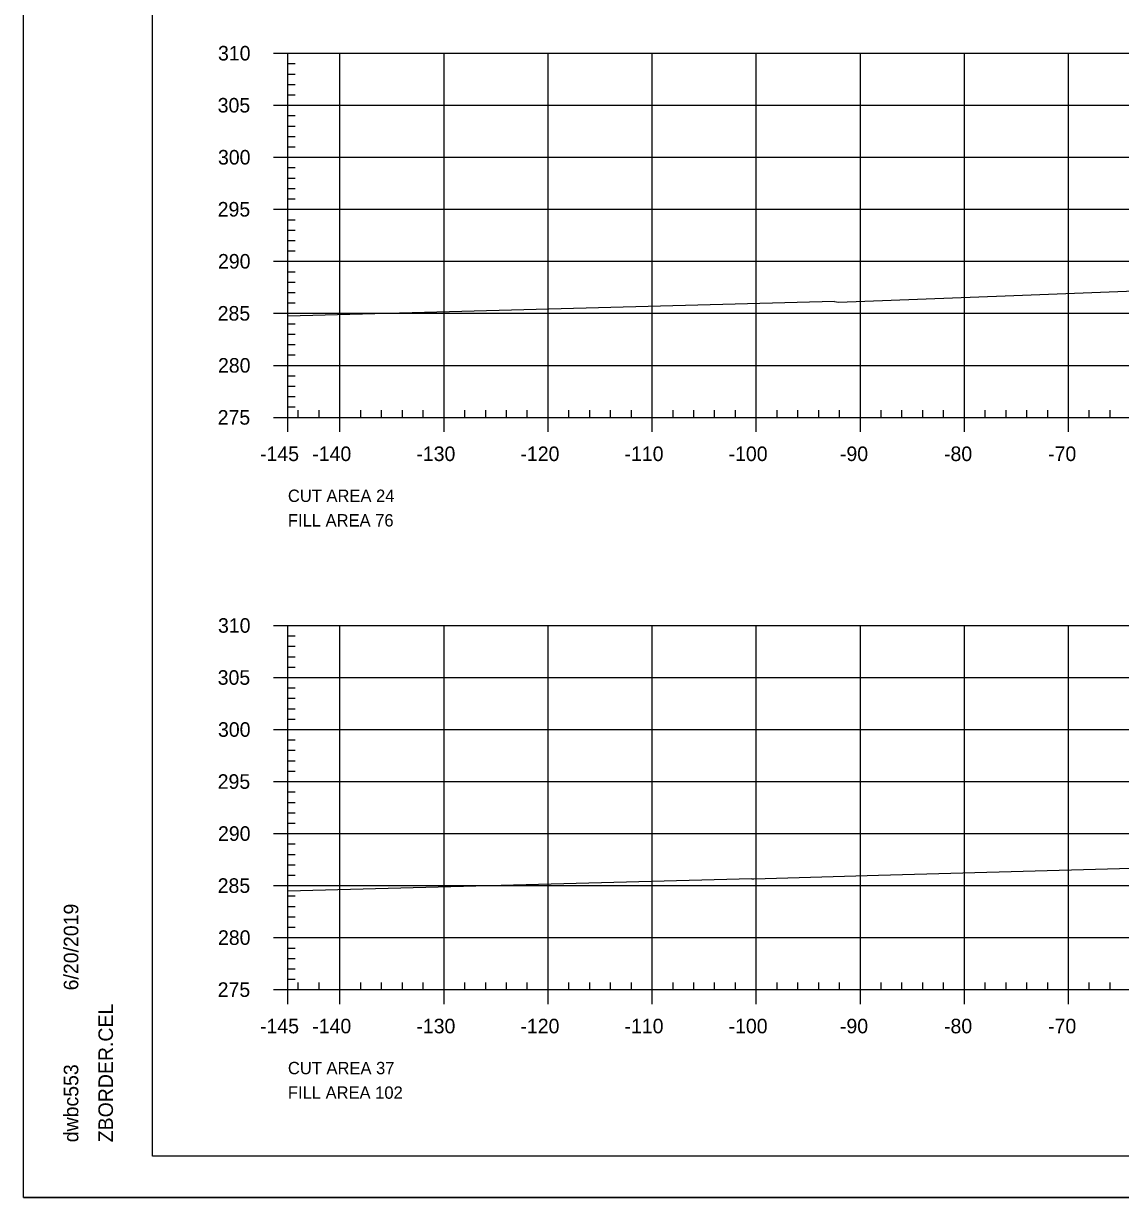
# Model space of a CAD drawing. Extents: x 1370843 to 1371177, y 380307 to 382654.
# Drawn here: x 1370843.3 to 1370948.7, y 382014.2 to 382127 of the extents above; entities that cross this region are included whole.
import ezdxf

# ---------------------------------------------------------------- set-up
doc = ezdxf.new("R2010")
doc.units = 0
for name, color, linetype in [('R_Axis', 7, 'Continuous'), ('R_Axis Annot', 7, 'Continuous'), ('R_Border', 7, 'Continuous'), ('R_Border Notes', 7, 'Continuous'), ('R_Exist Surface', 7, 'Continuous'), ('R_Grid', 7, 'Continuous'), ('R_No Plot', 7, 'Continuous')]:
    doc.layers.add(name, color=color, linetype=linetype)

msp = doc.modelspace()

# ---------------------------------------------------------------- linework, layer by layer
at = {"layer": 'R_Axis'}
for p, q in [((1370867.31, 382124.15), (1370868.71, 382124.15)), ((1370868.71, 382089.15), (1370868.71, 382124.15)), ((1370868.71, 382123.15), (1370869.41, 382123.15)), ((1370868.71, 382122.15), (1370869.41, 382122.15)), ((1370868.71, 382121.15), (1370869.41, 382121.15)), ((1370868.71, 382120.15), (1370869.41, 382120.15)), ((1370867.31, 382119.15), (1370868.71, 382119.15)), ((1370868.71, 382118.15), (1370869.41, 382118.15)), ((1370868.71, 382117.15), (1370869.41, 382117.15)), ((1370868.71, 382116.15), (1370869.41, 382116.15)), ((1370867.31, 382114.15), (1370868.71, 382114.15)), ((1370868.71, 382115.15), (1370869.41, 382115.15)), ((1370868.71, 382113.15), (1370869.41, 382113.15)), ((1370868.71, 382112.15), (1370869.41, 382112.15)), ((1370868.71, 382111.15), (1370869.41, 382111.15)), ((1370868.71, 382110.15), (1370869.41, 382110.15)), ((1370867.31, 382109.15), (1370868.71, 382109.15)), ((1370868.71, 382108.15), (1370869.41, 382108.15)), ((1370868.71, 382107.15), (1370869.41, 382107.15)), ((1370868.71, 382106.15), (1370869.41, 382106.15)), ((1370868.71, 382105.15), (1370869.41, 382105.15)), ((1370867.31, 382104.15), (1370868.71, 382104.15)), ((1370868.71, 382103.15), (1370869.41, 382103.15)), ((1370868.71, 382102.15), (1370869.41, 382102.15)), ((1370868.71, 382101.15), (1370869.41, 382101.15)), ((1370868.71, 382100.15), (1370869.41, 382100.15)), ((1370867.31, 382099.15), (1370868.71, 382099.15)), ((1370868.71, 382098.15), (1370869.41, 382098.15)), ((1370868.71, 382097.15), (1370869.41, 382097.15)), ((1370868.71, 382096.15), (1370869.41, 382096.15)), ((1370868.71, 382095.15), (1370869.41, 382095.15)), ((1370867.31, 382094.15), (1370868.71, 382094.15)), ((1370868.71, 382093.15), (1370869.41, 382093.15)), ((1370868.71, 382092.15), (1370869.41, 382092.15)), ((1370868.71, 382091.15), (1370869.41, 382091.15)), ((1370868.71, 382090.15), (1370869.41, 382090.15)), ((1370868.71, 382089.15), (1370868.71, 382089.85)), ((1370869.71, 382089.15), (1370869.71, 382089.85)), ((1370871.71, 382089.15), (1370871.71, 382089.85)), ((1370875.71, 382089.15), (1370875.71, 382089.85)), ((1370877.71, 382089.15), (1370877.71, 382089.85)), ((1370879.71, 382089.15), (1370879.71, 382089.85)), ((1370881.71, 382089.15), (1370881.71, 382089.85)), ((1370885.71, 382089.15), (1370885.71, 382089.85)), ((1370887.71, 382089.15), (1370887.71, 382089.85)), ((1370889.71, 382089.15), (1370889.71, 382089.85)), ((1370891.71, 382089.15), (1370891.71, 382089.85)), ((1370895.71, 382089.15), (1370895.71, 382089.85)), ((1370897.71, 382089.15), (1370897.71, 382089.85)), ((1370899.71, 382089.15), (1370899.71, 382089.85)), ((1370901.71, 382089.15), (1370901.71, 382089.85)), ((1370905.71, 382089.15), (1370905.71, 382089.85)), ((1370907.71, 382089.15), (1370907.71, 382089.85)), ((1370909.71, 382089.15), (1370909.71, 382089.85)), ((1370911.71, 382089.15), (1370911.71, 382089.85)), ((1370915.71, 382089.15), (1370915.71, 382089.85)), ((1370917.71, 382089.15), (1370917.71, 382089.85)), ((1370919.71, 382089.15), (1370919.71, 382089.85)), ((1370921.71, 382089.15), (1370921.71, 382089.85)), ((1370925.71, 382089.15), (1370925.71, 382089.85)), ((1370927.71, 382089.15), (1370927.71, 382089.85)), ((1370929.71, 382089.15), (1370929.71, 382089.85)), ((1370931.71, 382089.15), (1370931.71, 382089.85)), ((1370935.71, 382089.15), (1370935.71, 382089.85)), ((1370937.71, 382089.15), (1370937.71, 382089.85)), ((1370939.71, 382089.15), (1370939.71, 382089.85)), ((1370941.71, 382089.15), (1370941.71, 382089.85)), ((1370945.71, 382089.15), (1370945.71, 382089.85)), ((1370947.71, 382089.15), (1370947.71, 382089.85)), ((1370867.31, 382089.15), (1370868.71, 382089.15)), ((1370868.71, 382089.15), (1371158.71, 382089.15)), ((1370868.71, 382087.75), (1370868.71, 382089.15)), ((1370873.71, 382087.75), (1370873.71, 382089.15)), ((1370883.71, 382087.75), (1370883.71, 382089.15)), ((1370893.71, 382087.75), (1370893.71, 382089.15)), ((1370903.71, 382087.75), (1370903.71, 382089.15)), ((1370913.71, 382087.75), (1370913.71, 382089.15)), ((1370923.71, 382087.75), (1370923.71, 382089.15)), ((1370933.71, 382087.75), (1370933.71, 382089.15)), ((1370943.71, 382087.75), (1370943.71, 382089.15)), ((1370867.31, 382069.15), (1370868.71, 382069.15)), ((1370868.71, 382034.15), (1370868.71, 382069.15)), ((1370868.71, 382068.15), (1370869.41, 382068.15)), ((1370868.71, 382067.15), (1370869.41, 382067.15)), ((1370868.71, 382066.15), (1370869.41, 382066.15)), ((1370868.71, 382065.15), (1370869.41, 382065.15)), ((1370867.31, 382064.15), (1370868.71, 382064.15)), ((1370868.71, 382063.15), (1370869.41, 382063.15)), ((1370868.71, 382062.15), (1370869.41, 382062.15)), ((1370868.71, 382061.15), (1370869.41, 382061.15)), ((1370868.71, 382060.15), (1370869.41, 382060.15)), ((1370867.31, 382059.15), (1370868.71, 382059.15)), ((1370868.71, 382058.15), (1370869.41, 382058.15)), ((1370868.71, 382057.15), (1370869.41, 382057.15)), ((1370868.71, 382056.15), (1370869.41, 382056.15)), ((1370868.71, 382055.15), (1370869.41, 382055.15)), ((1370867.31, 382054.15), (1370868.71, 382054.15)), ((1370868.71, 382053.15), (1370869.41, 382053.15)), ((1370868.71, 382052.15), (1370869.41, 382052.15)), ((1370868.71, 382051.15), (1370869.41, 382051.15)), ((1370868.71, 382050.15), (1370869.41, 382050.15)), ((1370867.31, 382049.15), (1370868.71, 382049.15)), ((1370868.71, 382048.15), (1370869.41, 382048.15)), ((1370868.71, 382047.15), (1370869.41, 382047.15)), ((1370868.71, 382046.15), (1370869.41, 382046.15)), ((1370867.31, 382044.15), (1370868.71, 382044.15)), ((1370868.71, 382045.15), (1370869.41, 382045.15)), ((1370868.71, 382043.15), (1370869.41, 382043.15)), ((1370868.71, 382042.15), (1370869.41, 382042.15)), ((1370868.71, 382041.15), (1370869.41, 382041.15)), ((1370868.71, 382040.15), (1370869.41, 382040.15)), ((1370867.31, 382039.15), (1370868.71, 382039.15)), ((1370868.71, 382038.15), (1370869.41, 382038.15)), ((1370868.71, 382037.15), (1370869.41, 382037.15)), ((1370868.71, 382036.15), (1370869.41, 382036.15)), ((1370868.71, 382035.15), (1370869.41, 382035.15)), ((1370867.31, 382034.15), (1370868.71, 382034.15)), ((1370868.71, 382034.15), (1370868.71, 382034.85)), ((1370868.71, 382034.15), (1371158.71, 382034.15)), ((1370868.71, 382032.75), (1370868.71, 382034.15)), ((1370869.71, 382034.15), (1370869.71, 382034.85)), ((1370871.71, 382034.15), (1370871.71, 382034.85)), ((1370873.71, 382032.75), (1370873.71, 382034.15)), ((1370875.71, 382034.15), (1370875.71, 382034.85)), ((1370877.71, 382034.15), (1370877.71, 382034.85)), ((1370879.71, 382034.15), (1370879.71, 382034.85)), ((1370881.71, 382034.15), (1370881.71, 382034.85)), ((1370883.71, 382032.75), (1370883.71, 382034.15)), ((1370885.71, 382034.15), (1370885.71, 382034.85)), ((1370887.71, 382034.15), (1370887.71, 382034.85)), ((1370889.71, 382034.15), (1370889.71, 382034.85)), ((1370891.71, 382034.15), (1370891.71, 382034.85)), ((1370893.71, 382032.75), (1370893.71, 382034.15)), ((1370895.71, 382034.15), (1370895.71, 382034.85)), ((1370897.71, 382034.15), (1370897.71, 382034.85)), ((1370899.71, 382034.15), (1370899.71, 382034.85)), ((1370901.71, 382034.15), (1370901.71, 382034.85)), ((1370903.71, 382032.75), (1370903.71, 382034.15)), ((1370905.71, 382034.15), (1370905.71, 382034.85)), ((1370907.71, 382034.15), (1370907.71, 382034.85)), ((1370909.71, 382034.15), (1370909.71, 382034.85)), ((1370911.71, 382034.15), (1370911.71, 382034.85)), ((1370913.71, 382032.75), (1370913.71, 382034.15)), ((1370915.71, 382034.15), (1370915.71, 382034.85)), ((1370917.71, 382034.15), (1370917.71, 382034.85)), ((1370919.71, 382034.15), (1370919.71, 382034.85)), ((1370921.71, 382034.15), (1370921.71, 382034.85)), ((1370923.71, 382032.75), (1370923.71, 382034.15)), ((1370925.71, 382034.15), (1370925.71, 382034.85)), ((1370927.71, 382034.15), (1370927.71, 382034.85)), ((1370929.71, 382034.15), (1370929.71, 382034.85)), ((1370931.71, 382034.15), (1370931.71, 382034.85)), ((1370933.71, 382032.75), (1370933.71, 382034.15)), ((1370935.71, 382034.15), (1370935.71, 382034.85)), ((1370937.71, 382034.15), (1370937.71, 382034.85)), ((1370939.71, 382034.15), (1370939.71, 382034.85)), ((1370941.71, 382034.15), (1370941.71, 382034.85)), ((1370943.71, 382032.75), (1370943.71, 382034.15)), ((1370945.71, 382034.15), (1370945.71, 382034.85)), ((1370947.71, 382034.15), (1370947.71, 382034.85))]:
    msp.add_line(p, q, dxfattribs=at)
at = {"layer": 'R_Border'}
for p, q in [((1370855.71, 382018.15), (1370855.71, 382223.61)), ((1370855.71, 382018.15), (1370855.71, 382018.15)), ((1371171.89, 382018.15), (1370855.71, 382018.15))]:
    msp.add_line(p, q, dxfattribs=at)
at = {"layer": 'R_Exist Surface'}
for p, q in [((1370921.23, 382100.29), (1370868.71, 382098.89)), ((1370913.3, 382044.81), (1370868.71, 382043.61))]:
    msp.add_line(p, q, dxfattribs=at)
for points in [[(1370921.23, 382100.29), (1370921.61, 382100.23), (1370937.63, 382100.82), (1370961.82, 382101.77), (1370979.86, 382106.36), (1370981.34, 382106.74), (1370981.8, 382106.81), (1370987.82, 382107.67), (1370988.64, 382107.69), (1370999.17, 382107.94), (1370999.85, 382107.91), (1371008.58, 382107.56), (1371016.29, 382106.64), (1371016.42, 382106.63), (1371016.6, 382106.58), (1371022.64, 382105.04), (1371028.47, 382103.56), (1371028.64, 382103.51), (1371029, 382103.47), (1371041.26, 382102.03), (1371071.02, 382100.83), (1371076.66, 382100.61)], [(1370913.3, 382044.81), (1370913.49, 382044.81), (1370925.46, 382045.14), (1370954.42, 382045.95), (1370970.4, 382050.35), (1370975.86, 382051.82), (1370977.13, 382051.98), (1370981.24, 382052.53), (1370983.59, 382052.58), (1370992.86, 382052.74), (1370994.81, 382052.65), (1371001.83, 382052.35), (1371003.31, 382052.16), (1371009.26, 382051.49), (1371020.73, 382048.37), (1371022.75, 382047.86), (1371028.21, 382047.57), (1371072.46, 382046.77)]]:
    msp.add_lwpolyline(points, dxfattribs=at)
at = {"layer": 'R_Grid'}
for p, q in [((1370868.71, 382124.15), (1371158.71, 382124.15)), ((1370868.71, 382089.15), (1370868.71, 382124.15)), ((1370873.71, 382089.15), (1370873.71, 382124.15)), ((1370883.71, 382089.15), (1370883.71, 382124.15)), ((1370893.71, 382089.15), (1370893.71, 382124.15)), ((1370903.71, 382089.15), (1370903.71, 382124.15)), ((1370913.71, 382089.15), (1370913.71, 382124.15)), ((1370923.71, 382089.15), (1370923.71, 382124.15)), ((1370933.71, 382089.15), (1370933.71, 382124.15)), ((1370943.71, 382089.15), (1370943.71, 382124.15)), ((1370868.71, 382119.15), (1371158.71, 382119.15)), ((1370868.71, 382114.15), (1371158.71, 382114.15)), ((1370868.71, 382109.15), (1371158.71, 382109.15)), ((1370868.71, 382104.15), (1371158.71, 382104.15)), ((1370868.71, 382099.15), (1371158.71, 382099.15)), ((1370868.71, 382094.15), (1371158.71, 382094.15)), ((1370868.71, 382089.15), (1371158.71, 382089.15)), ((1370868.71, 382069.15), (1371158.71, 382069.15)), ((1370868.71, 382034.15), (1370868.71, 382069.15)), ((1370873.71, 382034.15), (1370873.71, 382069.15)), ((1370883.71, 382034.15), (1370883.71, 382069.15)), ((1370893.71, 382034.15), (1370893.71, 382069.15)), ((1370903.71, 382034.15), (1370903.71, 382069.15)), ((1370913.71, 382034.15), (1370913.71, 382069.15)), ((1370923.71, 382034.15), (1370923.71, 382069.15)), ((1370933.71, 382034.15), (1370933.71, 382069.15)), ((1370943.71, 382034.15), (1370943.71, 382069.15)), ((1370868.71, 382064.15), (1371158.71, 382064.15)), ((1370868.71, 382059.15), (1371158.71, 382059.15)), ((1370868.71, 382054.15), (1371158.71, 382054.15)), ((1370868.71, 382049.15), (1371158.71, 382049.15)), ((1370868.71, 382044.15), (1371158.71, 382044.15)), ((1370868.71, 382039.15), (1371158.71, 382039.15)), ((1370868.71, 382034.15), (1371158.71, 382034.15))]:
    msp.add_line(p, q, dxfattribs=at)
at = {"layer": 'R_No Plot'}
msp.add_line((1370843.31, 382014.17), (1371176.64, 382014.17), dxfattribs=at)
for points in [[(1370843.3, 382227.51), (1371176.64, 382227.51), (1371176.64, 382014.17), (1370843.3, 382014.17)], [(1371089.63, 382223.61), (1371089.63, 382213.73), (1371125.36, 382213.73), (1371125.36, 382210.81), (1371148.56, 382210.81), (1371148.56, 382186.48), (1371171.89, 382186.48), (1371171.89, 382018.15), (1370855.71, 382018.15), (1370855.71, 382223.61)]]:
    msp.add_lwpolyline(points, close=True, dxfattribs=at)

# ---------------------------------------------------------------- texts
at = {"layer": 'R_Axis Annot'}
for s, p in [('310', (1370861.99, 382123.45)), ('305', (1370861.96, 382118.45)), ('300', (1370861.99, 382113.45)), ('295', (1370861.96, 382108.45)), ('290', (1370861.99, 382103.45)), ('285', (1370861.96, 382098.45)), ('280', (1370861.99, 382093.45)), ('275', (1370861.96, 382088.45)), ('-145', (1370866.03, 382084.95)), ('-140', (1370871.05, 382084.95)), ('-130', (1370881.05, 382084.95)), ('-120', (1370891.05, 382084.95)), ('-110', (1370901.05, 382084.95)), ('-100', (1370911.05, 382084.95)), ('-90', (1370921.75, 382084.95)), ('-80', (1370931.75, 382084.95)), ('-70', (1370941.75, 382084.95)), ('310', (1370861.99, 382068.45)), ('305', (1370861.96, 382063.45)), ('300', (1370861.99, 382058.45)), ('295', (1370861.96, 382053.45)), ('290', (1370861.99, 382048.45)), ('285', (1370861.96, 382043.45)), ('280', (1370861.99, 382038.45)), ('275', (1370861.96, 382033.45)), ('-145', (1370866.03, 382029.95)), ('-140', (1370871.05, 382029.95)), ('-130', (1370881.05, 382029.95)), ('-120', (1370891.05, 382029.95)), ('-110', (1370901.05, 382029.95)), ('-100', (1370911.05, 382029.95)), ('-90', (1370921.75, 382029.95)), ('-80', (1370931.75, 382029.95)), ('-70', (1370941.75, 382029.95))]:
    msp.add_text(s, height=1.4, dxfattribs=at).set_placement(p)
at = {"layer": 'R_Border'}
for s, p in [('6/20/2019', (1370848.57, 382034.08)), ('ZBORDER.CEL', (1370851.9, 382019.48)), ('dwbc553', (1370848.57, 382019.48))]:
    msp.add_text(s, height=1.4, rotation=90, dxfattribs=at).set_placement(p)
at = {"layer": 'R_Border Notes'}
for s, p in [('CUT AREA 24', (1370868.71, 382081.02)), ('FILL AREA 76', (1370868.71, 382078.66)), ('CUT AREA 37', (1370868.71, 382026.02)), ('FILL AREA 102', (1370868.71, 382023.66))]:
    msp.add_text(s, height=1.1875, dxfattribs=at).set_placement(p)

doc.saveas('drawing.dxf')
